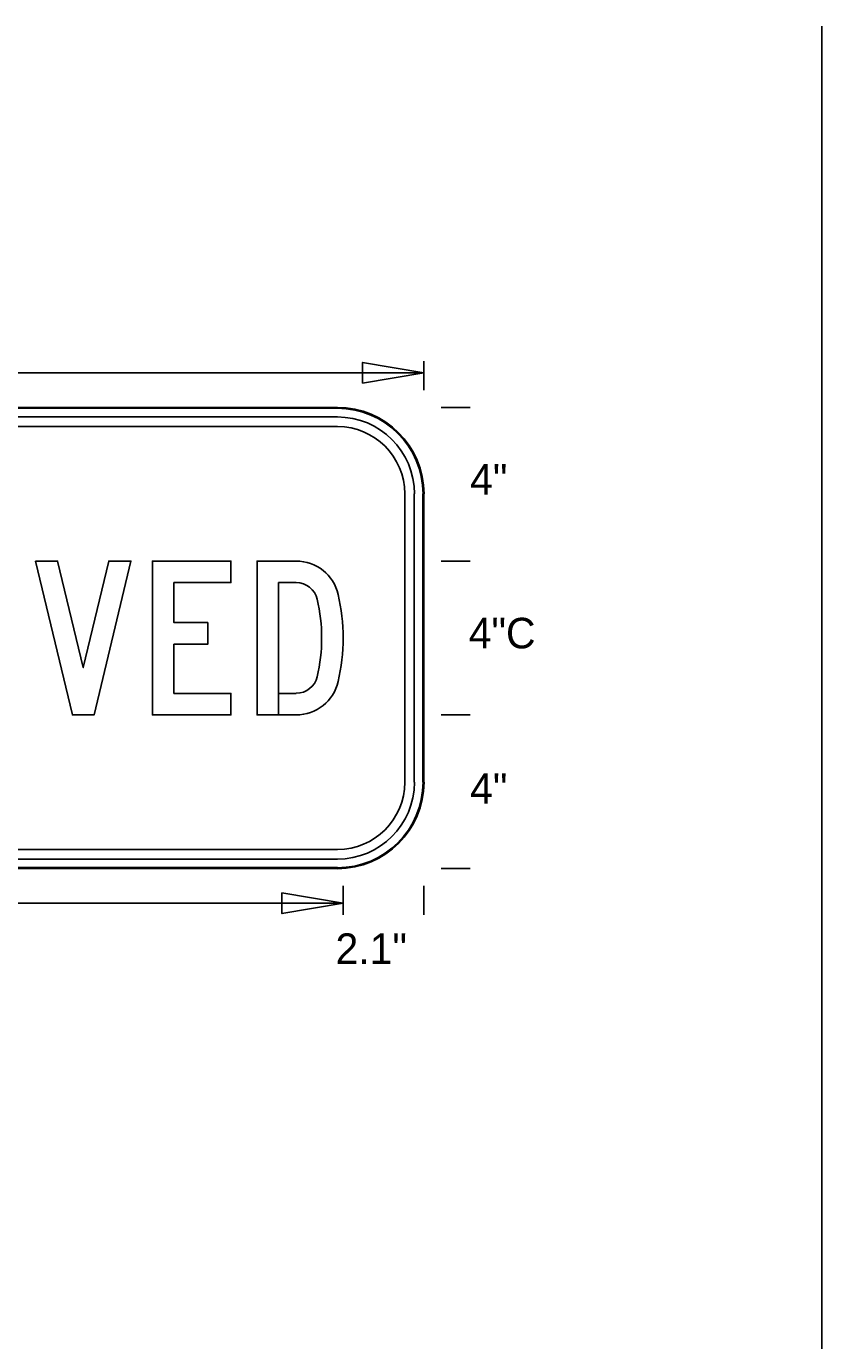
# Model space of a CAD drawing. Extents: x 0 to 770, y 0 to 495.
# Drawn here: x 294 to 385, y 344.6 to 495 of the extents above; entities that cross this region are included whole.
import ezdxf

# ---------------------------------------------------------------- set-up
doc = ezdxf.new("R2010")
doc.units = 0
for name, color, linetype in [('Dimension', 7, 'Continuous'), ('GSBWFill', 7, 'Continuous'), ('GSColorFill', 7, 'Continuous'), ('GSDims', 7, 'Continuous'), ('GSOutline', 7, 'Continuous'), ('SheetLines_dp', 7, 'Continuous'), ('TextStructures', 7, 'Continuous')]:
    doc.layers.add(name, color=color, linetype=linetype)

msp = doc.modelspace()

# ---------------------------------------------------------------- linework, layer by layer
at = {"layer": 'Dimension'}
for points in [[(339.51, 455.35), (332.5, 456.54), (332.5, 454.17)], [(330.28, 394.66), (323.26, 395.85), (323.26, 393.47)]]:
    msp.add_lwpolyline(points, close=True, dxfattribs=at)
at = {"layer": 'GSBWFill'}
for p, q in [((329.62, 451.4), (243.85, 451.4)), ((329.62, 450.3), (243.85, 450.3)), ((243.85, 449.2), (329.62, 449.2)), ((337.31, 441.5), (337.31, 408.51)), ((338.41, 408.51), (338.41, 441.5)), ((339.51, 408.51), (339.51, 441.5)), ((324.91, 418.67), (322.89, 418.67)), ((329.62, 400.82), (243.86, 400.82)), ((243.85, 398.62), (329.62, 398.62)), ((243.86, 399.72), (329.62, 399.72))]:
    msp.add_line(p, q, dxfattribs=at)
for points in [[(295.09, 433.8), (297.62, 433.8), (300.54, 421.63), (303.47, 433.8), (306, 433.8), (301.78, 416.21), (299.31, 416.21)], [(310.92, 418.67), (310.92, 424.3), (314.78, 424.3), (314.78, 426.77), (310.92, 426.77), (310.92, 431.34), (317.43, 431.34), (317.43, 433.8), (308.46, 433.8), (308.46, 416.21), (317.43, 416.21), (317.43, 418.67)]]:
    msp.add_lwpolyline(points, close=True, dxfattribs=at)
for points in [[(324.91, 433.8), (320.42, 433.8), (320.42, 416.21), (322.89, 416.21), (322.89, 431.34), (324.91, 431.34)], [(322.89, 418.67), (322.89, 416.21), (324.91, 416.21)]]:
    msp.add_lwpolyline(points, dxfattribs=at)
for centre, radius, start, end in [((329.62, 441.5), 9.9, 0, 90), ((329.62, 441.5), 8.8, 0, 90), ((329.62, 441.5), 7.7, 0, 90), ((324.91, 428.88), 4.93, 13.109, 90), ((324.91, 428.88), 2.46, 13.109, 90), ((308.28, 425.01), 19.53, 346.891, 13.109), ((308.28, 425.01), 21.99, 346.891, 13.109), ((324.91, 421.14), 2.46, 270, 346.891), ((324.91, 421.14), 4.93, 270, 346.891), ((329.62, 408.51), 8.8, 270, 0), ((329.62, 408.51), 7.7, 270, 0), ((329.62, 408.51), 9.9, 270, 0)]:
    msp.add_arc(centre, radius, start, end, dxfattribs=at)
at = {"layer": 'GSColorFill'}
for p, q in [((329.62, 451.4), (243.85, 451.4)), ((329.62, 451.4), (243.85, 451.4)), ((243.85, 451.29), (329.62, 451.29)), ((329.62, 450.3), (243.85, 450.3)), ((243.85, 449.2), (329.62, 449.2)), ((337.31, 441.5), (337.31, 408.51)), ((338.41, 408.51), (338.41, 441.5)), ((339.4, 441.5), (339.4, 408.51)), ((339.51, 408.51), (339.51, 441.5)), ((339.51, 408.51), (339.51, 441.5)), ((324.91, 418.67), (322.89, 418.67)), ((329.62, 400.82), (243.86, 400.82)), ((329.62, 398.73), (243.85, 398.73)), ((243.85, 398.62), (329.62, 398.62)), ((243.85, 398.62), (329.62, 398.62)), ((243.86, 399.72), (329.62, 399.72))]:
    msp.add_line(p, q, dxfattribs=at)
for points in [[(295.09, 433.8), (297.62, 433.8), (300.54, 421.63), (303.47, 433.8), (306, 433.8), (301.78, 416.21), (299.31, 416.21)], [(310.92, 418.67), (310.92, 424.3), (314.78, 424.3), (314.78, 426.77), (310.92, 426.77), (310.92, 431.34), (317.43, 431.34), (317.43, 433.8), (308.46, 433.8), (308.46, 416.21), (317.43, 416.21), (317.43, 418.67)]]:
    msp.add_lwpolyline(points, close=True, dxfattribs=at)
for points in [[(324.91, 433.8), (320.42, 433.8), (320.42, 416.21), (322.89, 416.21), (322.89, 431.34), (324.91, 431.34)], [(322.89, 418.67), (322.89, 416.21), (324.91, 416.21)]]:
    msp.add_lwpolyline(points, dxfattribs=at)
for centre, radius, start, end in [((329.62, 441.5), 9.9, 0, 90), ((329.62, 441.5), 9.9, 0, 90), ((329.62, 441.5), 9.79, 0, 90), ((329.62, 441.5), 8.8, 0, 90), ((329.62, 441.5), 7.7, 0, 90), ((324.91, 428.88), 4.93, 13.109, 90), ((324.91, 428.88), 2.46, 13.109, 90), ((308.28, 425.01), 19.53, 346.891, 13.109), ((308.28, 425.01), 21.99, 346.891, 13.109), ((324.91, 421.14), 2.46, 270, 346.891), ((324.91, 421.14), 4.93, 270, 346.891), ((329.62, 408.51), 9.9, 270, 0), ((329.62, 408.51), 8.8, 270, 0), ((329.62, 408.51), 7.7, 270, 0), ((329.62, 408.51), 9.9, 270, 0), ((329.62, 408.51), 9.79, 270, 0)]:
    msp.add_arc(centre, radius, start, end, dxfattribs=at)
at = {"layer": 'GSDims'}
for p, q in [((339.51, 453.38), (339.51, 456.67)), ((233.96, 455.35), (339.51, 455.35)), ((341.49, 451.4), (344.79, 451.4)), ((341.49, 433.8), (344.79, 433.8)), ((341.49, 433.8), (344.79, 433.8)), ((341.49, 416.21), (344.79, 416.21)), ((341.49, 416.21), (344.79, 416.21)), ((341.49, 398.62), (344.79, 398.62)), ((330.28, 396.64), (330.28, 393.34)), ((330.28, 396.64), (330.28, 393.34)), ((339.51, 396.64), (339.51, 393.34)), ((243.19, 394.66), (330.28, 394.66))]:
    msp.add_line(p, q, dxfattribs=at)
at = {"layer": 'GSOutline'}
for p, q in [((329.62, 451.4), (243.85, 451.4)), ((329.62, 450.3), (243.85, 450.3)), ((329.62, 449.2), (243.85, 449.2)), ((337.31, 408.51), (337.31, 441.5)), ((338.41, 408.51), (338.41, 441.5)), ((339.51, 408.51), (339.51, 441.5)), ((322.89, 418.67), (324.91, 418.67)), ((324.91, 416.21), (324.91, 416.21)), ((243.85, 400.82), (329.62, 400.82)), ((243.85, 399.72), (329.62, 399.72)), ((243.85, 398.62), (329.62, 398.62))]:
    msp.add_line(p, q, dxfattribs=at)
for points in [[(295.09, 433.8), (297.62, 433.8), (300.54, 421.63), (303.47, 433.8), (306, 433.8), (301.78, 416.21), (299.31, 416.21)], [(310.92, 418.67), (310.92, 424.3), (314.78, 424.3), (314.78, 426.77), (310.92, 426.77), (310.92, 431.34), (317.43, 431.34), (317.43, 433.8), (308.46, 433.8), (308.46, 416.21), (317.43, 416.21), (317.43, 418.67)]]:
    msp.add_lwpolyline(points, close=True, dxfattribs=at)
for points in [[(324.91, 433.8), (320.42, 433.8), (320.42, 416.21), (324.91, 416.21)], [(324.91, 431.34), (322.89, 431.34), (322.89, 418.67)]]:
    msp.add_lwpolyline(points, dxfattribs=at)
for centre, radius, start, end in [((329.62, 441.5), 9.9, 0, 90), ((329.62, 441.5), 8.8, 0, 90), ((329.62, 441.5), 7.7, 0, 90), ((324.91, 428.88), 4.93, 13.109, 90), ((324.91, 428.88), 2.46, 13.109, 90), ((308.28, 425.01), 19.53, 346.891, 13.109), ((308.28, 425.01), 21.99, 346.891, 13.109), ((324.91, 421.14), 2.46, 270, 346.891), ((324.91, 421.14), 4.93, 270, 346.891), ((329.62, 408.51), 8.8, 270, 0), ((329.62, 408.51), 7.7, 270, 0), ((329.62, 408.51), 9.9, 270, 0)]:
    msp.add_arc(centre, radius, start, end, dxfattribs=at)
at = {"layer": 'SheetLines_dp'}
msp.add_line((385, 0), (385, 495), dxfattribs=at)

# ---------------------------------------------------------------- texts
at = {"layer": 'TextStructures'}
for s, p in [('4"', (344.79, 441.42)), ('4"C', (344.63, 423.82)), ('4"', (344.79, 406.04)), ('2.1"', (329.4, 387.71))]:
    msp.add_text(s, height=3.5, dxfattribs=at).set_placement(p)

doc.saveas('drawing.dxf')
